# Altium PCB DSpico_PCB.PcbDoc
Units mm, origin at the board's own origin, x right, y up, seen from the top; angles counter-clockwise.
Board outline 27.22 x 32 mm, 4 copper layers (L1, L2-GND, L3-PW, L4), stack 0.77 mm thick; 44 components, 49 nets, 199 pads, 127 vias.
Unrouted connection lines stored in the file: 1.
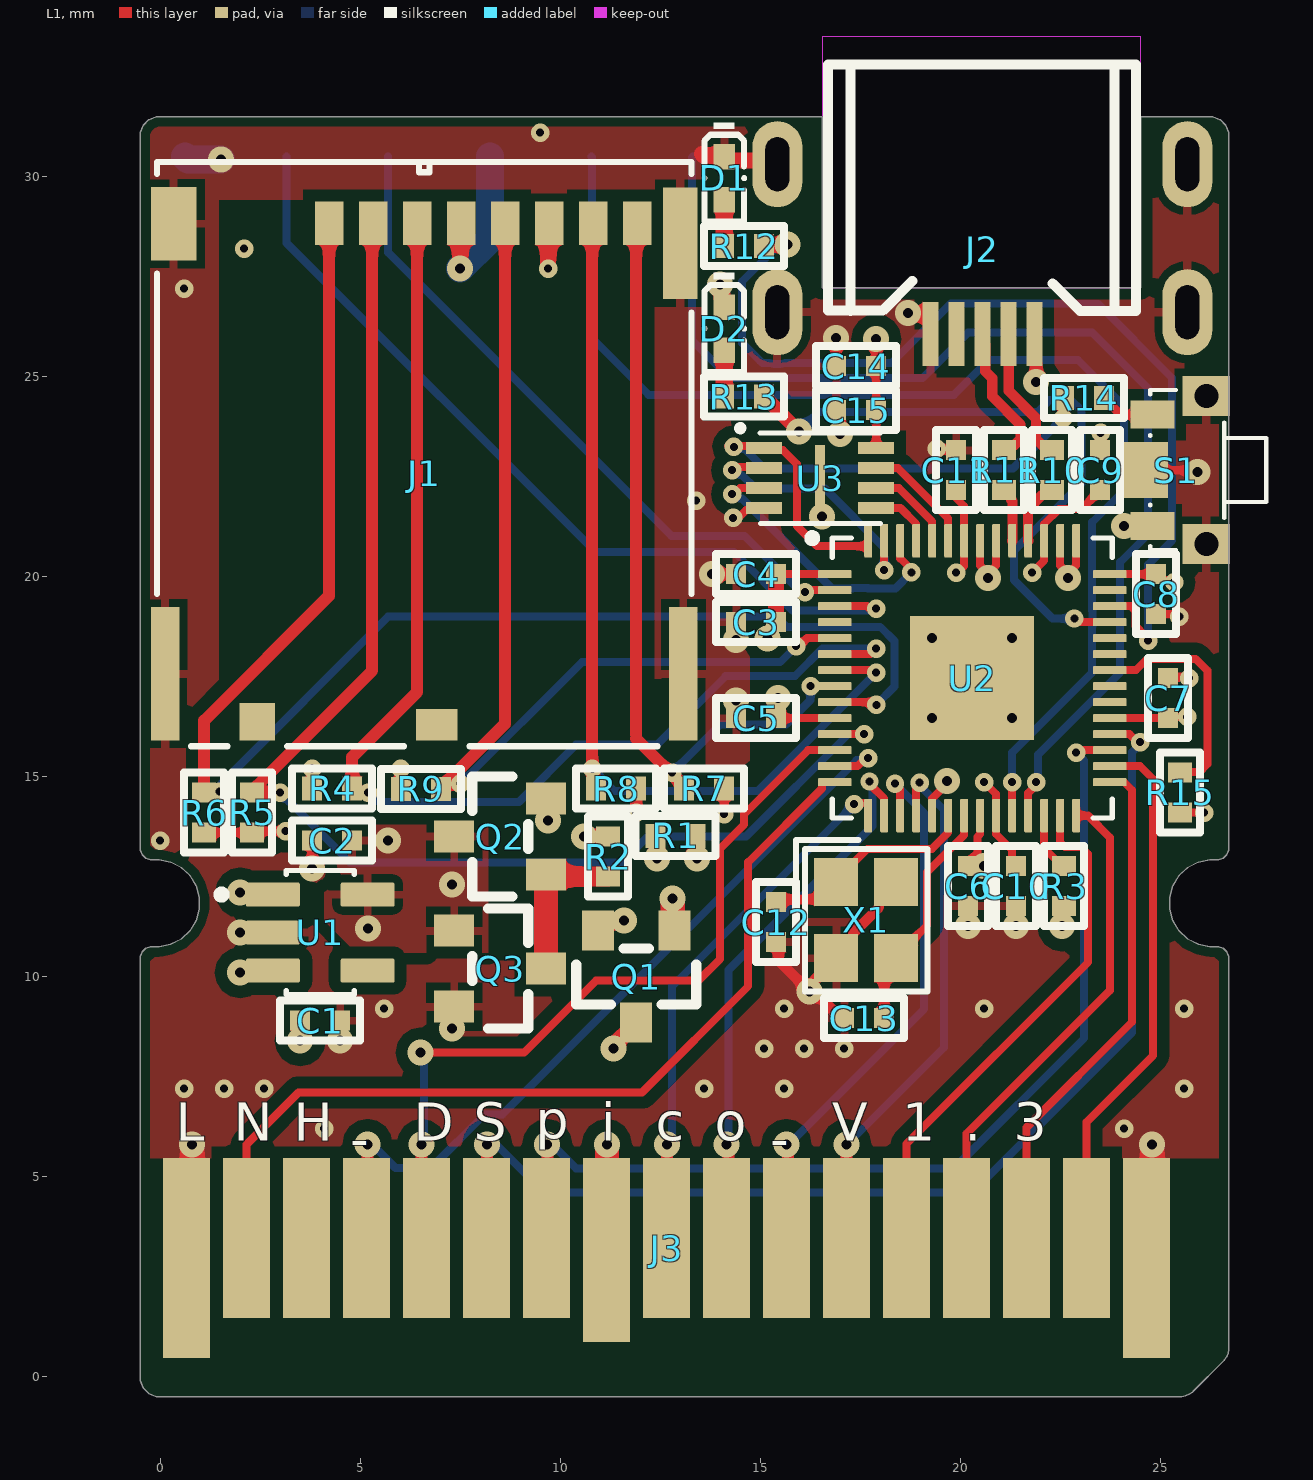
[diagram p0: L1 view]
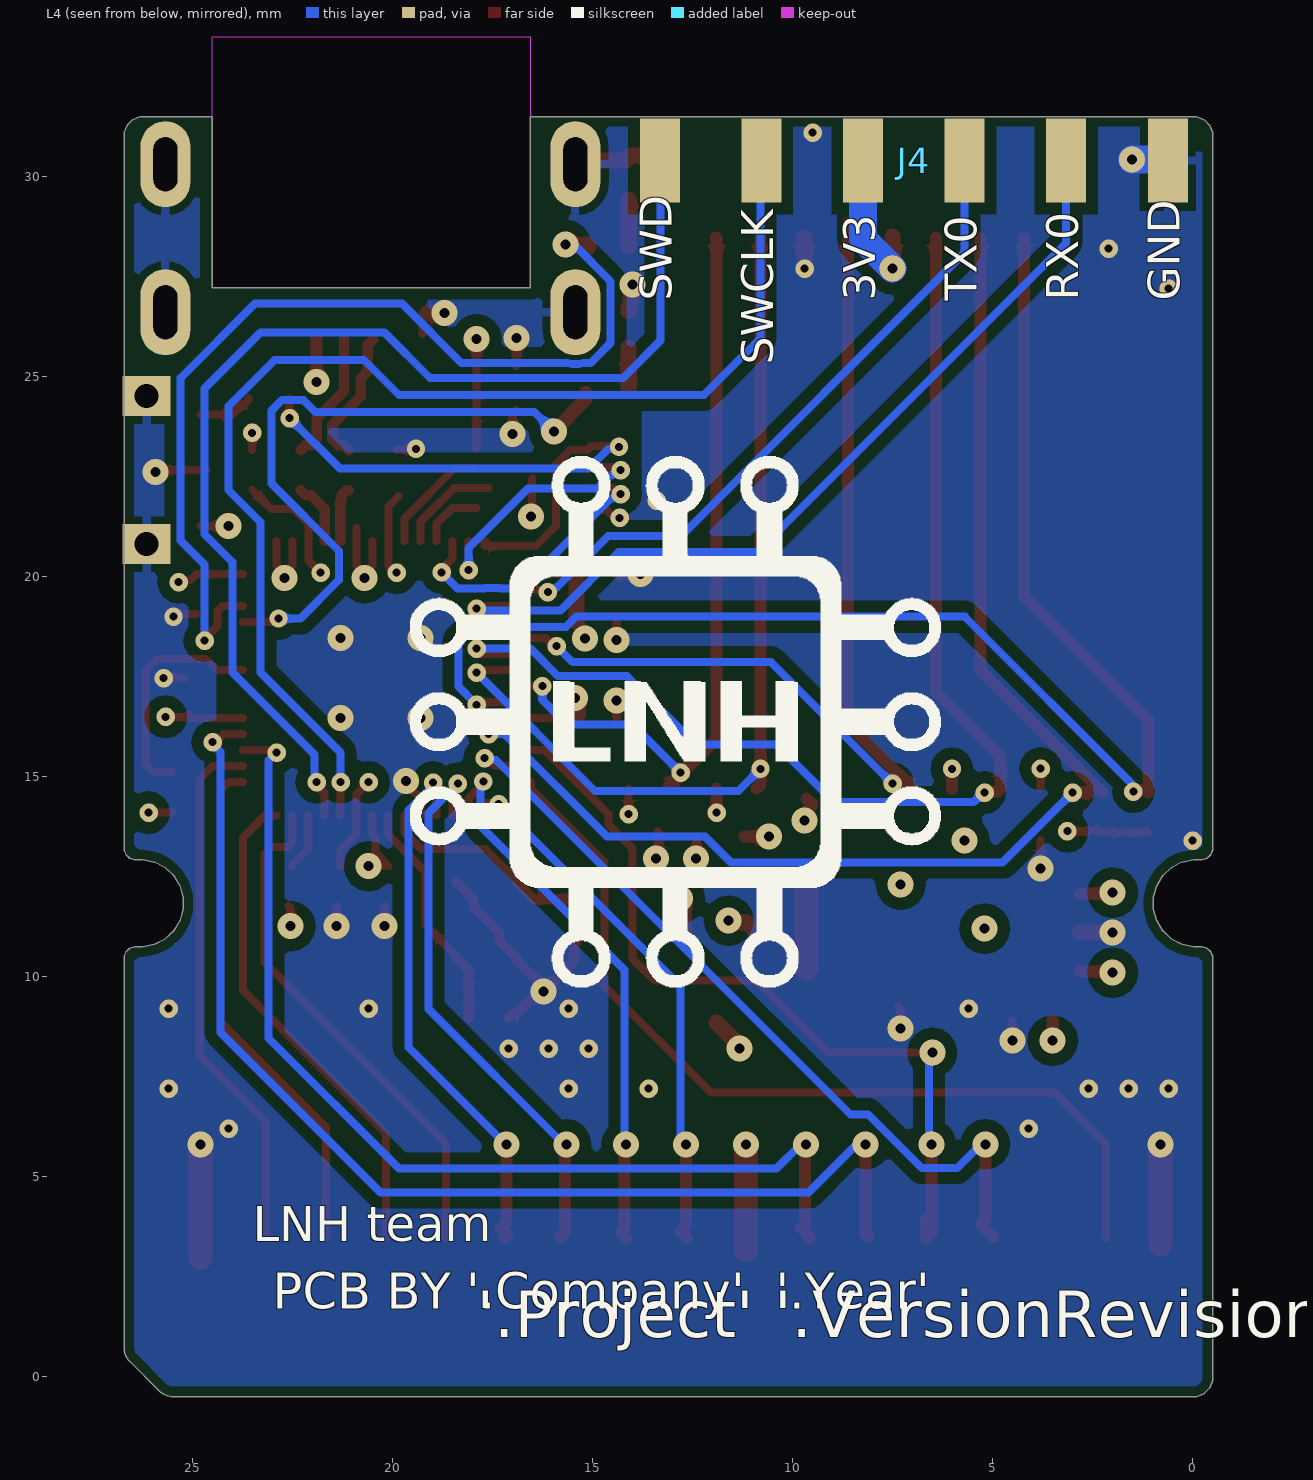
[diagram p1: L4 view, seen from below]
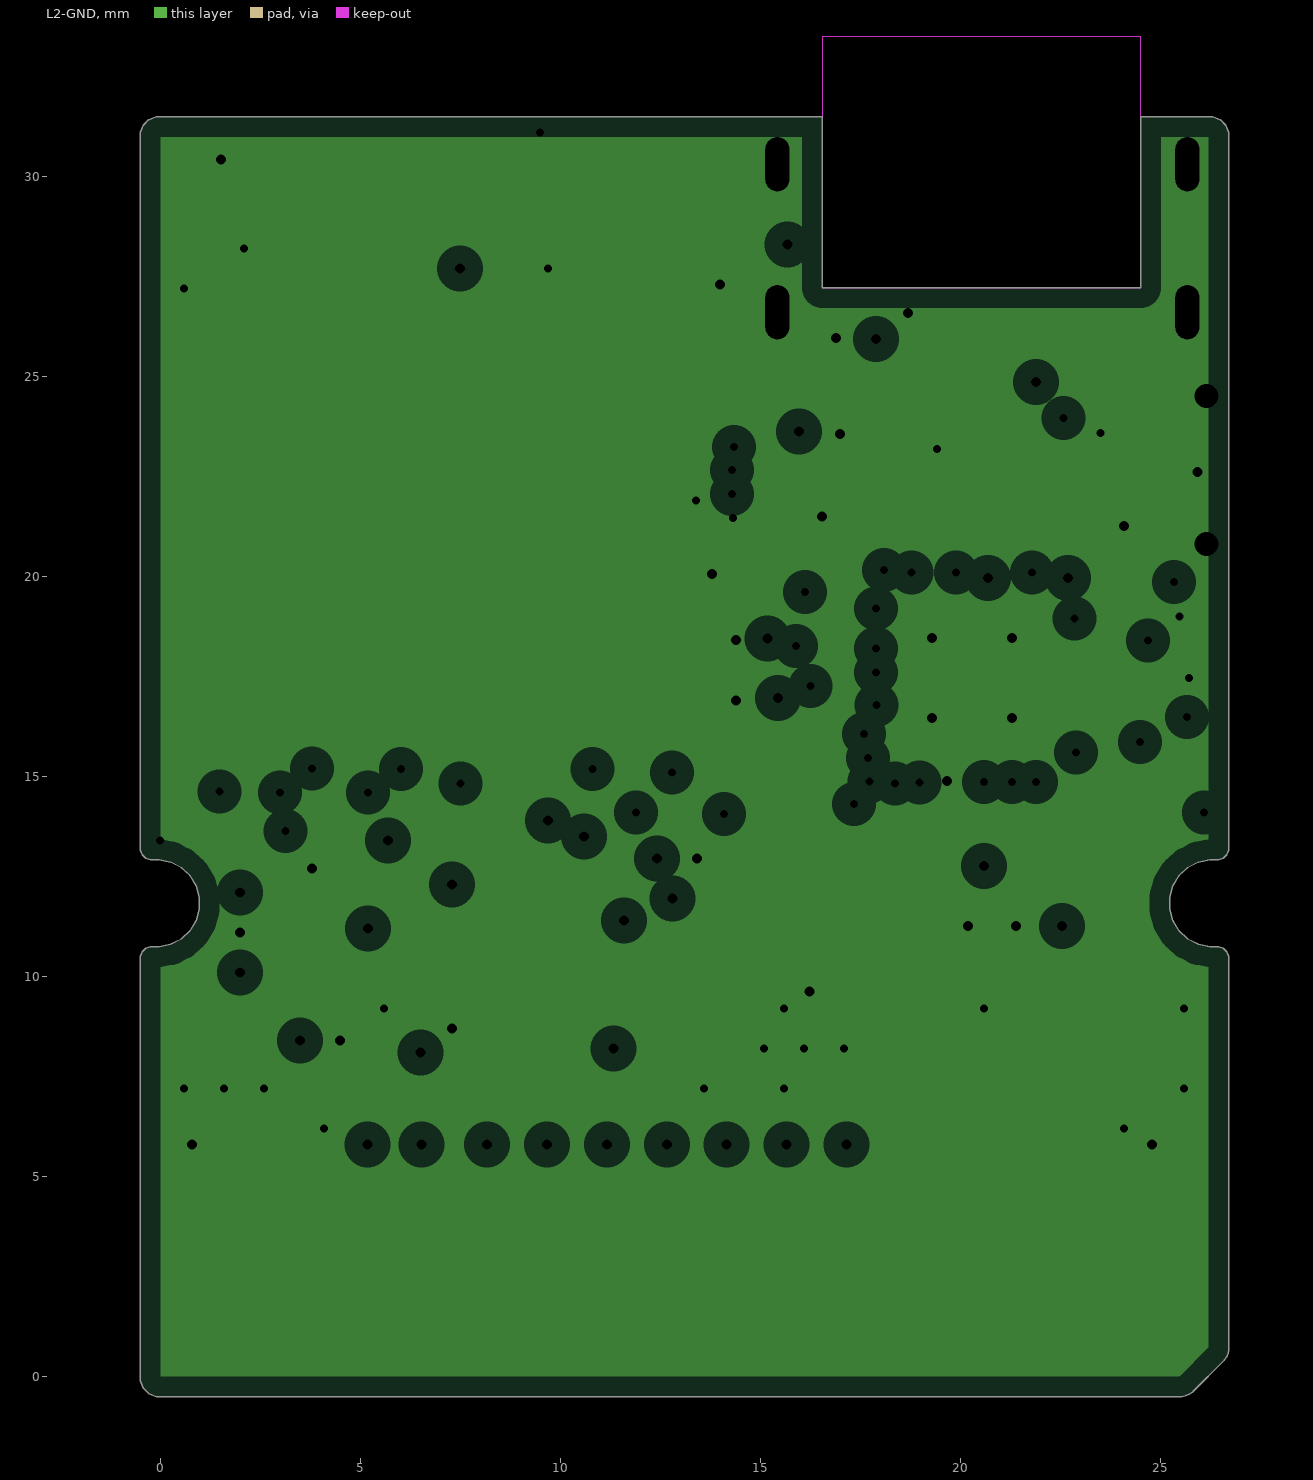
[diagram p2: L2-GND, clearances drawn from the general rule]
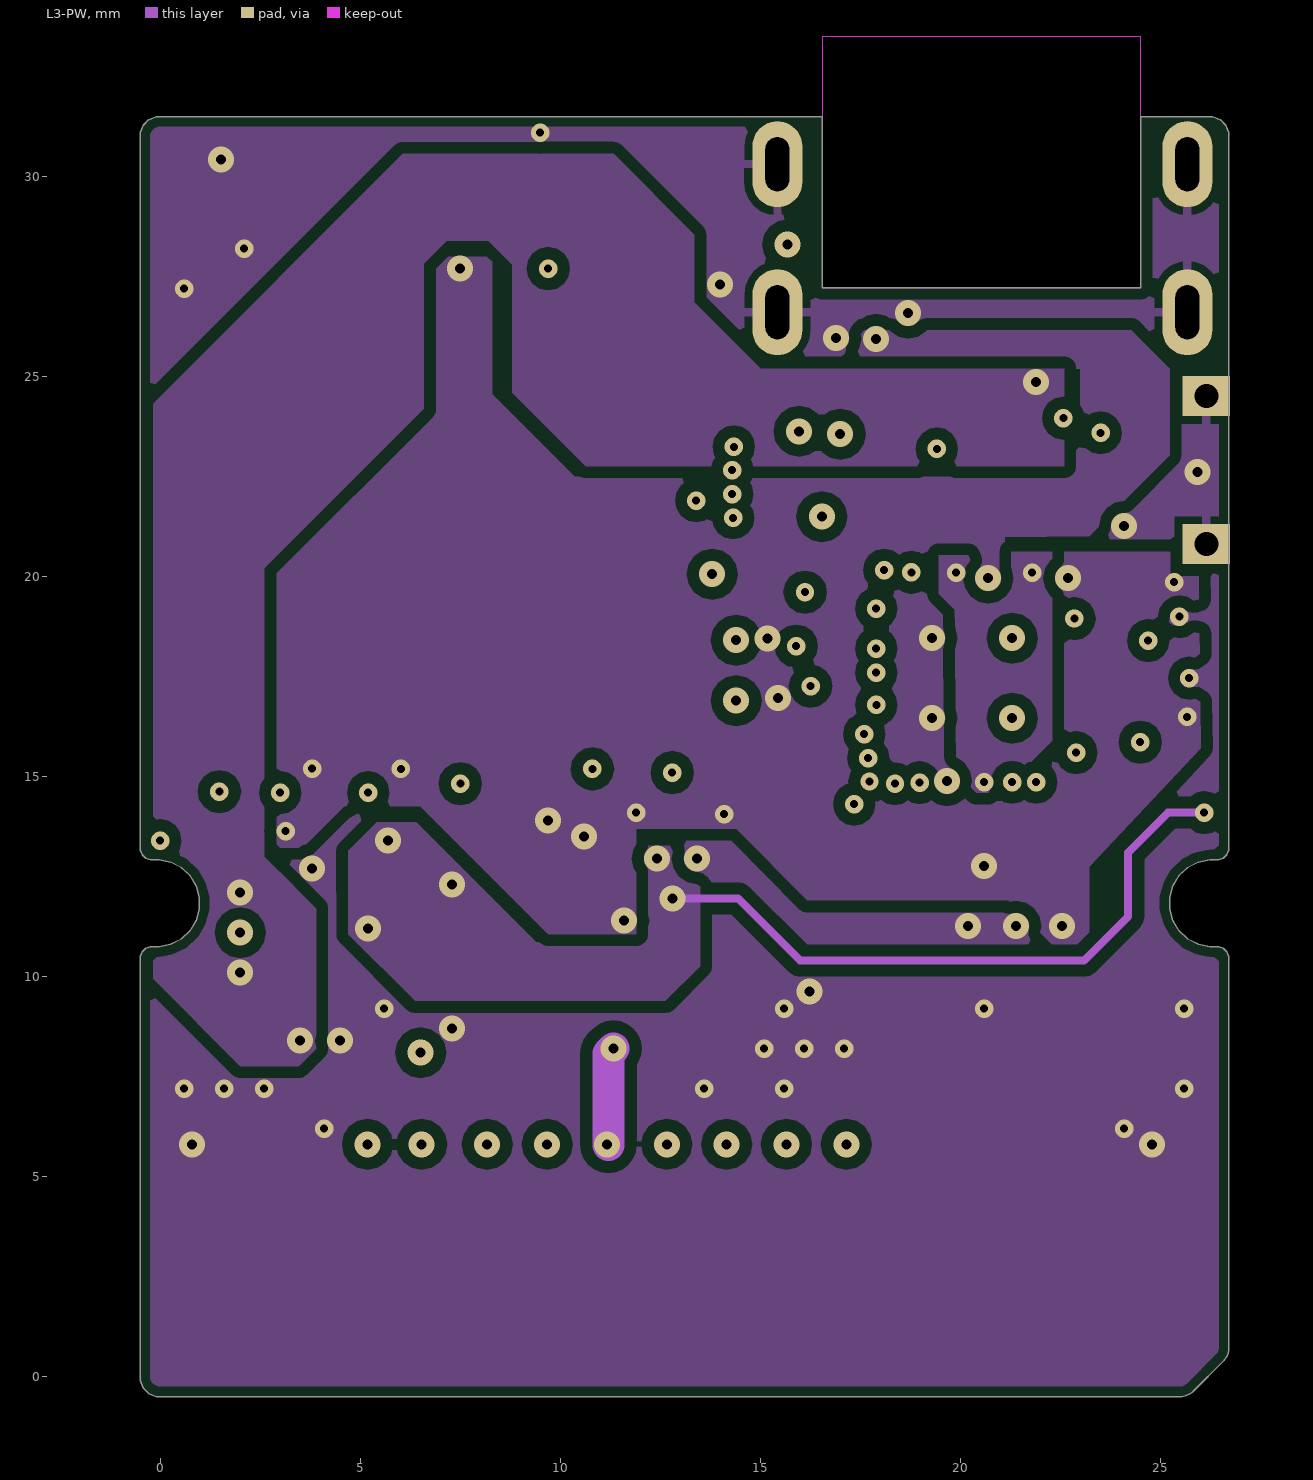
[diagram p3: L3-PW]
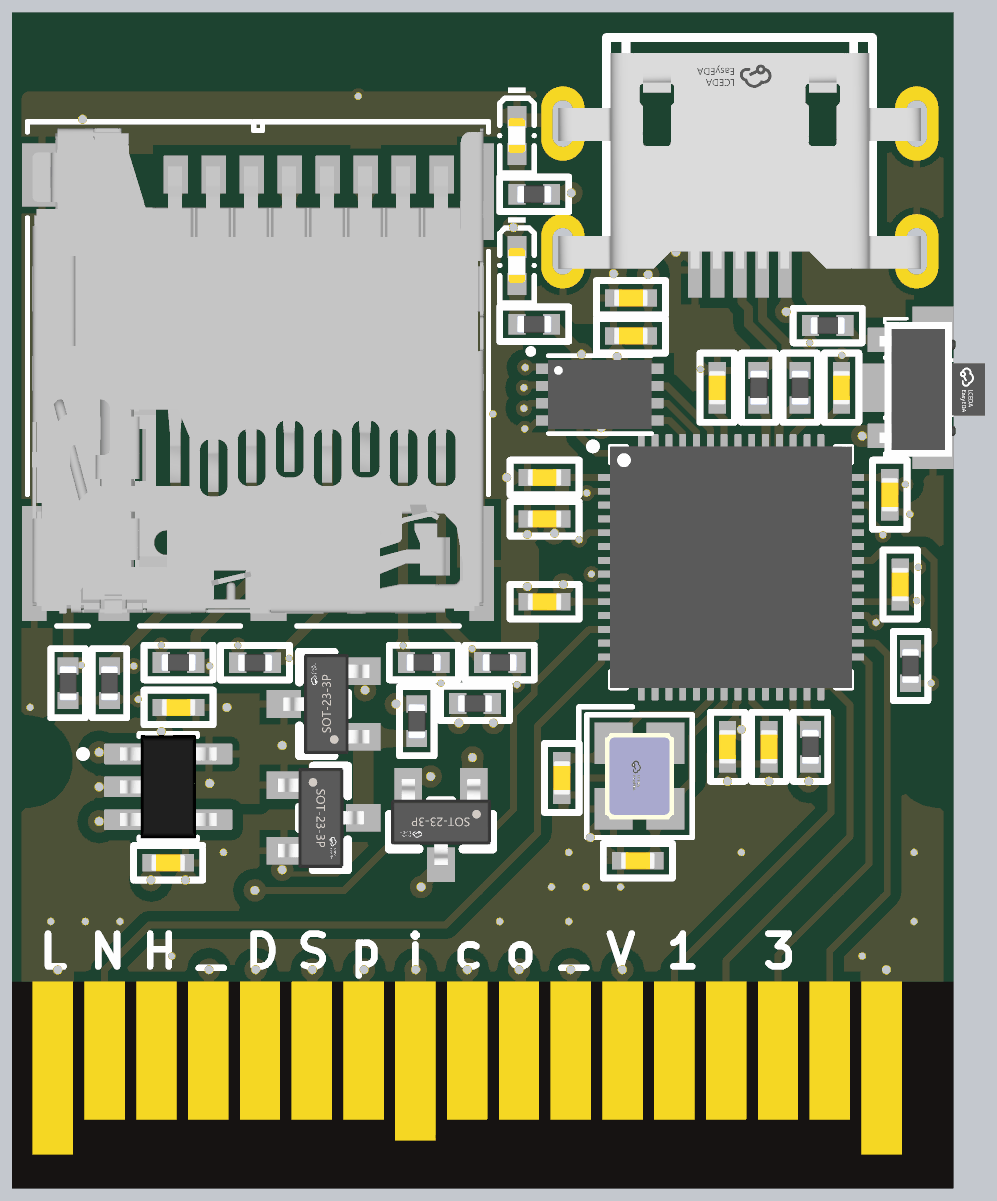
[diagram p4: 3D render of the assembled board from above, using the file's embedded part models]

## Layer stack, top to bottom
Top Solder: solder mask 0.01, Solder Resist, Dk 3.5
L1: signal copper 0.035
Dielectric 1: prepreg 0.21, PP-006, Dk 4.1
L2-GND: plane copper 0.015, net GND
Dielectric1: dielectric 0.25, FR-4, Dk 4.8
L3-PW: signal copper 0.015
Dielectric 2: prepreg 0.21, PP-006, Dk 4.1
L4: signal copper 0.035
Bottom Solder: solder mask 0.01, Solder Resist, Dk 3.5

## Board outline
-0.502,-0.101 -0.502,10.507 -0.452,10.621 -0.361,10.706 -0.243,10.748 -0.181,10.743 -0.032,10.743 0.26,10.803 0.525,10.94 0.743,11.143 0.898,11.398 0.978,11.684 0.978,11.982 0.898,12.269 0.743,12.523 0.525,12.727 0.26,12.863 -0.032,12.923 -0.181,12.923 -0.243,12.919 -0.361,12.96 -0.452,13.045 -0.502,13.16 -0.502,13.222 -0.502,31.099 -0.426,31.283 -0.285,31.424 -0.101,31.5 16.554,31.5 16.554,27.224 24.511,27.224 24.511,31.5 26.314,31.5 26.498,31.424 26.638,31.283 26.715,31.099 26.715,13.16 26.665,13.045 26.573,12.96 26.456,12.919 26.393,12.923 26.244,12.923 25.952,12.863 25.688,12.727 25.47,12.523 25.315,12.269 25.234,11.982 25.234,11.684 25.315,11.398 25.47,11.143 25.688,10.94 25.952,10.803 26.244,10.743 26.393,10.743 26.456,10.748 26.573,10.706 26.665,10.621 26.715,10.507 26.715,0.678 26.695,0.582 26.658,0.491 26.603,0.409 26.568,0.374 25.839,-0.355 25.804,-0.39 25.722,-0.445 25.631,-0.483 25.534,-0.502 25.485,-0.502 -0.002,-0.502 -0.101,-0.502 -0.285,-0.426 -0.426,-0.285

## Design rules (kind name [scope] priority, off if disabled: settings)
BoardOutlineClearance [All] p1: gap=0.25 ignorepadtopadclearanceinfootprint=FALSE except(0: Arc-SplitContinuation Track-SplitContinuation SMDPad-SplitContinuation THPad-SplitContinuation Via-SplitContinuation Fill-SplitContinuation Poly-SplitContinuation Region-SplitContinuation Text-SplitContinuation)
Clearance "Clearance poly Power Polygon" [OnLayer('L4-PWR') vs InPolygon] p1: gap=0.4 ignorepadtopadclearanceinfootprint=FALSE
Clearance Clearance-xPP-xTP-xTT [All] p2: gap=0.3 ignorepadtopadclearanceinfootprint=FALSE except(0: Arc-Hole Track-Hole SMDPad-Hole THPad-Hole Via-Hole Fill-Hole Poly-Hole Region-Hole Text-Hole; 0.125: Arc-Arc Arc-Track Arc-SMDPad Arc-THPad Arc-Via Track-Track Track-SMDPad Track-THPad Track-Via SMDPad-SMDPad SMDPad-THPad SMDPad-Via THPad-THPad THPad-Via Via-Via; 0.15: Arc-Text Track-Text SMDPad-Text THPad-Text Via-Text Fill-Text Poly-Text Region-Text Text-Text)
ComponentClearance [All] p1: gap=0 collisioncheckmode=3 verticalgap=0 showdistances=FALSE
DiffPairsRouting DiffPairsRouting_USB [All] p1: maxlimit=0.254 minlimit=0.1 mostfreqgap=0.127 toplayer_mingap=0.126 toplayer_minwidth=0.26 toplayer_maxwidth=0.861 toplayer_prefwidth=0.26 midlayer1_minwidth=0.143 midlayer1_maxwidth=0.499 midlayer1_prefwidth=0.143 bottomlayer_mingap=0.126 bottomlayer_minwidth=0.26 bottomlayer_maxwidth=0.861 bottomlayer_prefwidth=0.26 substack1={DAE5CF59-E0D9-4D6D-B9BE-EB67B8F47C43} toplayer_{dae5cf59-e0d9-4d6d-b9be-eb67b8f47c43}_mingap=0.254 toplayer_{dae5cf59-e0d9-4d6d-b9be-eb67b8f47c43}_prefgap=0.254 toplayer_{dae5cf59-e0d9-4d6d-b9be-eb67b8f47c43}_minwidth=0.26 toplayer_{dae5cf59-e0d9-4d6d-b9be-eb67b8f47c43}_maxwidth=0.861 toplayer_{dae5cf59-e0d9-4d6d-b9be-eb67b8f47c43}_prefwidth=0.26 midlayer1_{dae5cf59-e0d9-4d6d-b9be-eb67b8f47c43}_mingap=0.254 midlayer1_{dae5cf59-e0d9-4d6d-b9be-eb67b8f47c43}_prefgap=0.254 midlayer1_{dae5cf59-e0d9-4d6d-b9be-eb67b8f47c43}_minwidth=0.143 midlayer1_{dae5cf59-e0d9-4d6d-b9be-eb67b8f47c43}_maxwidth=0.499 midlayer1_{dae5cf59-e0d9-4d6d-b9be-eb67b8f47c43}_prefwidth=0.143 bottomlayer_{dae5cf59-e0d9-4d6d-b9be-eb67b8f47c43}_mingap=0.254 bottomlayer_{dae5cf59-e0d9-4d6d-b9be-eb67b8f47c43}_prefgap=0.254 bottomlayer_{dae5cf59-e0d9-4d6d-b9be-eb67b8f47c43}_minwidth=0.26 bottomlayer_{dae5cf59-e0d9-4d6d-b9be-eb67b8f47c43}_maxwidth=0.861 bottomlayer_{dae5cf59-e0d9-4d6d-b9be-eb67b8f47c43}_prefwidth=0.26 substack2={701B8A70-685D-4FFA-A794-EED23E6922A1} toplayer_{701b8a70-685d-4ffa-a794-eed23e6922a1}_mingap=0.254 toplayer_{701b8a70-685d-4ffa-a794-eed23e6922a1}_prefgap=0.254 toplayer_{701b8a70-685d-4ffa-a794-eed23e6922a1}_minwidth=0.26 toplayer_{701b8a70-685d-4ffa-a794-eed23e6922a1}_maxwidth=0.861 toplayer_{701b8a70-685d-4ffa-a794-eed23e6922a1}_prefwidth=0.26 midlayer1_{701b8a70-685d-4ffa-a794-eed23e6922a1}_mingap=0.254 midlayer1_{701b8a70-685d-4ffa-a794-eed23e6922a1}_prefgap=0.254 midlayer1_{701b8a70-685d-4ffa-a794-eed23e6922a1}_minwidth=0.143 midlayer1_{701b8a70-685d-4ffa-a794-eed23e6922a1}_maxwidth=0.499 midlayer1_{701b8a70-685d-4ffa-a794-eed23e6922a1}_prefwidth=0.143 bottomlayer_{701b8a70-685d-4ffa-a794-eed23e6922a1}_mingap=0.254 bottomlayer_{701b8a70-685d-4ffa-a794-eed23e6922a1}_prefgap=0.254 bottomlayer_{701b8a70-685d-4ffa-a794-eed23e6922a1}_minwidth=0.26 bottomlayer_{701b8a70-685d-4ffa-a794-eed23e6922a1}_maxwidth=0.861 bottomlayer_{701b8a70-685d-4ffa-a794-eed23e6922a1}_prefwidth=0.26 substack3={F6D6EC32-38D3-4AFD-B5CD-3CE99868ACF7} toplayer_{f6d6ec32-38d3-4afd-b5cd-3ce99868acf7}_mingap=0.254 toplayer_{f6d6ec32-38d3-4afd-b5cd-3ce99868acf7}_prefgap=0.254 toplayer_{f6d6ec32-38d3-4afd-b5cd-3ce99868acf7}_minwidth=0.26 toplayer_{f6d6ec32-38d3-4afd-b5cd-3ce99868acf7}_maxwidth=0.861 toplayer_{f6d6ec32-38d3-4afd-b5cd-3ce99868acf7}_prefwidth=0.26 midlayer1_{f6d6ec32-38d3-4afd-b5cd-3ce99868acf7}_mingap=0.254 midlayer1_{f6d6ec32-38d3-4afd-b5cd-3ce99868acf7}_prefgap=0.254 midlayer1_{f6d6ec32-38d3-4afd-b5cd-3ce99868acf7}_minwidth=0.143 midlayer1_{f6d6ec32-38d3-4afd-b5cd-3ce99868acf7}_maxwidth=0.499 midlayer1_{f6d6ec32-38d3-4afd-b5cd-3ce99868acf7}_prefwidth=0.143 bottomlayer_{f6d6ec32-38d3-4afd-b5cd-3ce99868acf7}_mingap=0.254 bottomlayer_{f6d6ec32-38d3-4afd-b5cd-3ce99868acf7}_prefgap=0.254 bottomlayer_{f6d6ec32-38d3-4afd-b5cd-3ce99868acf7}_minwidth=0.26 bottomlayer_{f6d6ec32-38d3-4afd-b5cd-3ce99868acf7}_maxwidth=0.861 bottomlayer_{f6d6ec32-38d3-4afd-b5cd-3ce99868acf7}_prefwidth=0.26 substack4={6221F06C-9483-4E26-967B-27528F2B8686} toplayer_{6221f06c-9483-4e26-967b-27528f2b8686}_mingap=0.254 toplayer_{6221f06c-9483-4e26-967b-27528f2b8686}_prefgap=0.254 toplayer_{6221f06c-9483-4e26-967b-27528f2b8686}_minwidth=0.26 toplayer_{6221f06c-9483-4e26-967b-27528f2b8686}_maxwidth=0.861 toplayer_{6221f06c-9483-4e26-967b-27528f2b8686}_prefwidth=0.26 midlayer1_{6221f06c-9483-4e26-967b-27528f2b8686}_mingap=0.254 midlayer1_{6221f06c-9483-4e26-967b-27528f2b8686}_prefgap=0.254 midlayer1_{6221f06c-9483-4e26-967b-27528f2b8686}_minwidth=0.143 midlayer1_{6221f06c-9483-4e26-967b-27528f2b8686}_maxwidth=0.499 midlayer1_{6221f06c-9483-4e26-967b-27528f2b8686}_prefwidth=0.143 bottomlayer_{6221f06c-9483-4e26-967b-27528f2b8686}_mingap=0.254 bottomlayer_{6221f06c-9483-4e26-967b-27528f2b8686}_prefgap=0.254 bottomlayer_{6221f06c-9483-4e26-967b-27528f2b8686}_minwidth=0.26 bottomlayer_{6221f06c-9483-4e26-967b-27528f2b8686}_maxwidth=0.861 bottomlayer_{6221f06c-9483-4e26-967b-27528f2b8686}_prefwidth=0.26 impedanceprofiledriven=TRUE impedanceprofileid={773E90AA-7B5E-4F0F-963B-D0F3BC933954} impedanceprofilevalue=90.000000 maxuncoupledlength=12.7
Height [All] p1: minheight=0 maxheight=25 prefheight=12.5
HoleSize HoleSize-PTH [All] p1: absolutevalues=TRUE maxlimit=4 minlimit=0.15 maxpercent=80.000 minpercent=20.000
HoleToHoleClearance [All] p1: gap=0.35 allowstackedmicrovias=TRUE
MatchedLengths MatchedLengths_USB_DiffPairs_1 [InxSignalClass('USB_CHJ1_1_DL') OR InxSignalClass('USB_CHJ1_1_RX') OR InxSignalClass('USB_CHJ1_1_TX')] p1: tolerance=0.127 checknetsindiffpair=TRUE checkdiffpairvsdiffpair=FALSE checkxsignals=FALSE checkothers=FALSE
MatchedLengths MatchedLengths_USB_DiffPairs [InxSignalClass('USB_CHJ1_1_DL') OR InxSignalClass('USB_CHJ1_1_RX') OR InxSignalClass('USB_CHJ1_1_TX')] p2: tolerance=0.127 checknetsindiffpair=TRUE checkdiffpairvsdiffpair=FALSE checkxsignals=FALSE checkothers=FALSE
MatchedLengths DiffPairClass [InDifferentialPairClass('All Differential Pairs')] p3: tolerance=0.127 checknetsindiffpair=TRUE checkdiffpairvsdiffpair=FALSE checkxsignals=FALSE checkothers=FALSE
MatchedLengths MatchedLengths_GBE0 [InNetClass('GBE0')] p4: tolerance=0.127 checknetsindiffpair=FALSE checkdiffpairvsdiffpair=TRUE checkxsignals=TRUE checkothers=TRUE
MatchedLengths MatchedLengths_GBE1 [InNetClass('GBE1')] p5: tolerance=0.127 checknetsindiffpair=FALSE checkdiffpairvsdiffpair=TRUE checkxsignals=TRUE checkothers=TRUE
MatchedLengths MatchedLengths_GBE2 [InNetClass('GBE2')] p6: tolerance=0.127 checknetsindiffpair=FALSE checkdiffpairvsdiffpair=TRUE checkxsignals=TRUE checkothers=TRUE
MatchedLengths MatchedLengths_HDMI [InNetClass('HDMI')] p7: tolerance=0.127 checknetsindiffpair=FALSE checkdiffpairvsdiffpair=TRUE checkxsignals=TRUE checkothers=TRUE
MatchedLengths MatchedLengths_USB-GBE [InNetClass('USB-GBE')] p8: tolerance=0.127 checknetsindiffpair=FALSE checkdiffpairvsdiffpair=TRUE checkxsignals=TRUE checkothers=TRUE
MatchedLengths MatchedLengths_USB3 [InNetClass('USB3')] p9: tolerance=0.127 checknetsindiffpair=FALSE checkdiffpairvsdiffpair=TRUE checkxsignals=TRUE checkothers=TRUE
MatchedLengths MatchedLengths_USB2 [InNetClass('USB2')] p10: tolerance=0.127 checknetsindiffpair=FALSE checkdiffpairvsdiffpair=TRUE checkxsignals=TRUE checkothers=TRUE
MatchedLengths MatchedLengths_DS [InNetClass('D[7..0]')] p11: tolerance=0.127 checknetsindiffpair=FALSE checkdiffpairvsdiffpair=TRUE checkxsignals=TRUE checkothers=TRUE
MinimumAnnularRing "Minimum IAR  >0.45mm" [((ObjectKind = 'Pad') OR (ObjectKind = 'Via')) And (Layer = 'MultiLayer') And (HoleDiameter > AsMM(0.45))] p1: minimumring=0.13 // minimum inner annular ring for pads > 0.45mm finished hole size
MinimumAnnularRing "Minimum IAR <=0.45mm" [((ObjectKind = 'Pad') OR (ObjectKind = 'Via')) And (Layer = 'MultiLayer') And (HoleDiameter <= AsMM(0.45))] p2: minimumring=0.13 // minimum inner annular ring for pads <= 0.45mm finished hole size
MinimumSolderMaskSliver [All] p1: minsoldermaskwidth=0.08
PlaneClearance PlaneClearance-IPI [All] p1: clearance=0.45
PlaneConnect PlaneConnect_PWR [HasFootprint('NDS_CARD')] p1: planeconnectstyle=Direct reliefexpansion=0.175 reliefentries=2 reliefconductorwidth=0.2 reliefairgap=0.2
PlaneConnect PlaneConnect_NDS [HasFootprint('NDS_CARD')] p2: planeconnectstyle=Direct reliefexpansion=0.175 reliefentries=2 reliefconductorwidth=0.2 reliefairgap=0.2
PlaneConnect PlaneConnect_VIA [IsVia] p3: planeconnectstyle=Direct reliefexpansion=0.175 reliefentries=4 reliefconductorwidth=0.2 reliefairgap=0.2
PlaneConnect [All] p4: planeconnectstyle=Relief reliefexpansion=0.2 reliefentries=4 reliefconductorwidth=0.25 reliefairgap=0.2
PolygonConnect PolygonConnect_VIA [HasFootprint('NET_TIE')] p1: connectstyle=Direct reliefconductorwidth=0.2 reliefentries=4 polygonreliefangle="90 Angle" airgapwidth=0.2
PolygonConnect PolygonConnect_NDS [HasFootprint('NDS_CARD')] p2: connectstyle=Direct reliefconductorwidth=0.2 reliefentries=4 polygonreliefangle="90 Angle" airgapwidth=0.2
PolygonConnect PolygonConnect_VIA_1 [All] p3: thpad.connectstyle=Relief thpad.reliefconductorwidth=0.2 thpad.reliefentries=4 thpad.polygonreliefangle="90 Angle" thpad.airgapwidth=0.2 smdpad.connectstyle=Relief smdpad.reliefconductorwidth=0.2 smdpad.reliefentries=4 smdpad.polygonreliefangle="90 Angle" smdpad.airgapwidth=0.2 via.connectstyle=Direct via.reliefconductorwidth=0.2 via.reliefentries=4 via.polygonreliefangle="90 Angle" via.airgapwidth=0.2
PolygonConnect PolygonConnect_SMD [Not HasFootprint('NET_TIE') and InNet('AGND')] p4: thpad.connectstyle=Direct thpad.reliefconductorwidth=0.2 thpad.reliefentries=4 thpad.polygonreliefangle="90 Angle" thpad.airgapwidth=0.2 smdpad.connectstyle=Relief smdpad.reliefconductorwidth=0.2 smdpad.reliefentries=4 smdpad.polygonreliefangle="90 Angle" smdpad.airgapwidth=0.2 via.connectstyle=Direct via.reliefconductorwidth=0.2 via.reliefentries=4 via.polygonreliefangle="90 Angle" via.airgapwidth=0.2
PolygonConnect [All] p5: connectstyle=Relief reliefconductorwidth=0.25 reliefentries=4 polygonreliefangle="90 Angle" airgapwidth=0.2
RoutingCorners [All] p1: cornerstyle=45-Degree minsetback=2.5 maxsetback=2.5
RoutingVias "RoutingVias > 0.45mm" [(ObjectKind = 'Via') And (HoleDiameter > AsMM(0.45))] p1: holewidth=0.5 width=0.85 viastyle="Through Hole" minholewidth=0.5 minwidth=0.85 maxholewidth=0.9 maxwidth=1.25 // finishet hole size > 0.45mm
RoutingVias "RoutingVias <= 0.45mm" [(ObjectKind = 'Via') And (HoleDiameter <= AsMM(0.45))] p2: holewidth=0.2 width=0.55 viastyle="Through Hole" minholewidth=0.15 minwidth=0.5 maxholewidth=0.45 maxwidth=0.8 // finishet hole size <= 0.45mm
SilkToSilkClearance [All] p1: silktosilkclearance=0.1
SilkToSolderMaskClearance SilkscreenOverComponentPads [IsPad] p1: minsilkscreentomaskgap=0.1 clearancetoexposedcopper=TRUE
SolderMaskExpansion [All] p1: expansion=0 istentingtop=FALSE
UnRoutedNet [All] p1: checkbadconnections=TRUE
Width Width-xTW [All] p1: maxlimit=5 minlimit=0.125 preferedwidth=0.15
Width Width-GigaE [All] p2: maxlimit=0.15 minlimit=0.15 preferedwidth=0.15
Width Width-Power [InNetClass('PWR')] p3: maxlimit=5 minlimit=0.2 preferedwidth=0.25
18 further rules are at their usual default settings.

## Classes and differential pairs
net class D[7..0]: D0 D1 D2 D3 D4 D5 D6 D7
differential pair D: +D_P -D_N
differential pair USB_D: +USB_D_P -USB_D_N

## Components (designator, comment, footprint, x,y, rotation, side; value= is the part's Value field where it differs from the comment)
C1 "1uF" C0402 4,8.9 r180 top
C2 "1uF" C0402 4.3,13.4 r0 top
C3 "1uF" C0402 14.9,18.86 r0 top
C4 "100NF" C0402 14.9,20.06 r0 top
C5 "100NF" C0402 14.9,16.46 r0 top
C6 "100NF" C0402 20.2,12.26 r90 top
C7 "100NF" C0402 25.2,16.96 r270 top
C8 "100NF" C0402 24.9,19.56 r90 top
C9 "1uF" C0402 23.5,22.66 r270 top
C10 "100NF" C0402 21.4,12.26 r90 top
C11 "100NF" C0402 19.9,22.66 r270 top
C12 "12PF" C0402 15.4,11.36 r90 top
C13 "12PF" C0402 17.6,8.96 r0 top
C14 "2.2uF" C0402 17.4,25.26 r0 top
C15 "100NF" C0402 17.4,24.16 r0 top
D1 "BL-HB337A-AV-TRB" LED0402-RD 14.1,29.96 r270 top
D2 "BL-HUB37A-AV-TRB" LED0402-RD 14.1,26.2 r270 top
J1 "5033981892" 503398-1892_MOL 6.6,23.06 r0 top
J2 "920-F62A2021S10101" MICRO-USB_MICRO-USB-31 20.2,29.86 r90 top locked
J3 "NDS_CARDA" NDS_CARD 0.659,2.959 r0 top
J4 "DSPICO-DEV-PORT" EP_DEV_PORT 13.32,30.4 r180 bottom
Q1 "SI2307CDS-T1-E3" SOT-23_L2.9-W1.3-P1.90-LS2.4-BR 11.9,10 r90 top
Q2 "SI2307CDS-T1-E3" SOT-23_L2.9-W1.3-P1.90-LS2.4-BR 8.5,13.5 r0 top locked
Q3 "2N7002KQ-7" SOT-23_L2.9-W1.3-P1.90-LS2.4-BR 8.5,10.2 r180 top
R1 "100K" R0402 12.883,13.517 r0 top
R2 "100K" R0402 11.2,13 r90 top
R3 "10K" R0402 22.6,12.26 r270 top
R4 "10K" R0402 4.3,14.7 r180 top
R5 "10K" R0402 2.3,14.1 r270 top
R6 "10K" R0402 1.1,14.1 r270 top
R7 "10K" R0402 13.6,14.7 r0 top
R8 "10K" R0402 11.4,14.7 r0 top
R9 "10K" R0402 6.516,14.695 r180 top
R10 "RC0402FR-0727RL" R0402 22.3,22.66 r270 top value=27
R11 "RC0402FR-0727RL" R0402 21.1,22.66 r270 top value=27
R12 "120R" R0402 14.6,28.26 r0 top
R13 "220R" R0402 14.6,24.5 r0 top
R14 "1K" R0402 23.1,24.46 r180 top
R15 "1K" R0402 25.5,14.6 r90 top
S1 "SKTDLDE010" KEY-SMD_SKTDLDE010 25.4,22.66 r270 top
U1 "AP2112K-3.3TRG1" SOT95P285X140-5N 4,11.1 r0 top
U2 "RP2040" QFN40P700X700X90-57N 20.3,17.46 r0 top locked
U3 "W25Q16JVUXIQ" SON50P300X200X60-9N 16.5,22.46 r0 top
X1 "XYDBPCNANF-12MHZ" OSC-SMD_4P-L2.5-W2.0-BL 17.65,11.41 r270 top

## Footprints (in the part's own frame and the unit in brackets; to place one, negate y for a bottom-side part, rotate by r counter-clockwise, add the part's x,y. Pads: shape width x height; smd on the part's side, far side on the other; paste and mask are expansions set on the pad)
503398-1892_MOL [mil]
  rect 28x43 smd: 1(-93.7,227.38) 2(-50.39,227.38) 3(-7.09,227.38) 4(36.22,227.38) 5(79.53,227.38) 6(122.83,227.38) 7(166.14,227.38) 8(209.45,227.38)
  rect 35x37 smd: 9(-164.17,-263.37)
  rect 41x31 smd: 10(12.2,-266.32)
  rect 45x72 smd: 11(-246.46,226.79)
  rect 34x110 smd: 12(251.97,207.7)
  rect 28x131 smd: 13(-255.12,-216.12) 14(255.12,-216.12)
  silkscreen extent -263,-288 263,288, body extent -258,-273 258,280, height 50
C0402 [mm]
  rect 0.5x0.5 smd: 1(-0.5,0) 2(0.5,0)
  silkscreen extent -1,-0.5 1,0.5, body extent -0.5,-0.25 0.5,0.25, height 0.56
EP_DEV_PORT [mm] "Exposed DSpico Development port"
  rect 1x2.1 smd paste-1: 1(0,0) 2(2.54,0) 3(5.08,0) 4(7.62,0) 5(10.16,0) 6(12.7,0)
KEY-SMD_SKTDLDE010 [mm]
  rect 0.7x1.1 smd: 1(1.39,-0.596) 2(-1.388,-0.597)
  rect 1.4x1.1 smd: 3(0,-0.75)
  rect 1x1.2 hole 0.6: 4(-1.85,0.75) 4(1.85,0.75)
  silkscreen extent -2,-0.65 2,2.25, body extent -1.9,-0.8 2,2.25, height 1.54
LED0402-RD [mm]
  rect 0.636x0.54 smd: 1(-0.538,0) 2(0.538,0)
  silkscreen extent -1.39,-0.54 1.09,0.54, body extent -0.51,-0.26 0.51,0.25, height 0.19
MICRO-USB_MICRO-USB-31 [mm]
  rect 1.6x0.4 smd: 1(-3.791,-1.655) 2(-3.791,-1.005) 3(-3.791,-0.354) 4(-3.791,0.296) 5(-3.791,0.946)
  oval 2.15x1.25 hole 0.6 slot 1.35 at 0 deg: 6(-3.251,-5.479) 7(0.449,-5.479) 8(-3.251,4.771) 9(0.449,4.771)
  Keep-Out Layer board cut-out: -2.637,3.646 -2.637,-4.311 3.638,-4.311 3.638,3.646
  silkscreen extent -3.22,-4.19 2.94,3.51, body extent -3.75,-5.6 2.5,4.9, height 1.78
NDS_CARD [mm] "NDS_CARD"
  rect 1.17x5 smd paste-1: 1(0,0) 17(24,0)
  rect 1.17x4 smd paste-1: 2(1.5,0.5) 3(3,0.5) 4(4.5,0.5) 5(6,0.5) 6(7.5,0.5) 7(9,0.5) 9(12,0.5) 10(13.5,0.5) 11(15,0.5) 12(16.5,0.5) 13(18,0.5) 14(19.5,0.5) 15(21,0.5) 16(22.5,0.5)
  rect 1.17x4.6 smd paste-1: 8(10.5,0.2)
  L1 pour cut-out: -1.575,2.5 26.65,2.5 26.65,-3.975 -1.575,-3.975
OSC-SMD_4P-L2.5-W2.0-BL [mm]
  rect 1.2x1.1 smd: 1(-0.95,-0.75) 2(0.95,-0.75) 3(0.95,0.75) 4(-0.95,0.75)
  silkscreen extent -2.01,-1.76 1.78,1.53, body extent -1.25,-1 1.25,1, height 0.55
QFN40P700X700X90-57N [mm]
  rrect25% 0.84x0.2 smd: 1(-3.435,2.6) 2(-3.435,2.2) 3(-3.435,1.8) 4(-3.435,1.4) 5(-3.435,1) 6(-3.435,0.6) 7(-3.435,0.2) 8(-3.435,-0.2) 9(-3.435,-0.6) 10(-3.435,-1) 11(-3.435,-1.4) 12(-3.435,-1.8) 13(-3.435,-2.2) 14(-3.435,-2.6) 29(3.435,-2.6) 30(3.435,-2.2) 31(3.435,-1.8) 32(3.435,-1.4) 33(3.435,-1) 34(3.435,-0.6) 35(3.435,-0.2) 36(3.435,0.2) 37(3.435,0.6) 38(3.435,1) 39(3.435,1.4) 40(3.435,1.8) 41(3.435,2.2) 42(3.435,2.6)
  rrect25% 0.2x0.84 smd: 15(-2.6,-3.435) 16(-2.2,-3.435) 17(-1.8,-3.435) 18(-1.4,-3.435) 19(-1,-3.435) 20(-0.6,-3.435) 21(-0.2,-3.435) 22(0.2,-3.435) 23(0.6,-3.435) 24(1,-3.435) 25(1.4,-3.435) 26(1.8,-3.435) 27(2.2,-3.435) 28(2.6,-3.435) 43(2.6,3.435) 44(2.2,3.435) 45(1.8,3.435) 46(1.4,3.435) 47(1,3.435) 48(0.6,3.435) 49(0.2,3.435) 50(-0.2,3.435) 51(-0.6,3.435) 52(-1,3.435) 53(-1.4,3.435) 54(-1.8,3.435) 55(-2.2,3.435) 56(-2.6,3.435)
  rect 3.1x3.1 smd paste-0.57: 57(0,0)
  silkscreen extent -4.1,-3.5 3.5,3.6, body extent -3.5,-3.5 3.5,3.5, height 0.9
R0402 [mm]
  rect 0.5x0.6 smd: 1(-0.5,0) 2(0.5,0)
  silkscreen extent -1,-0.5 1,0.5, body extent -0.5,-0.25 0.5,0.25, height 0.4
SON50P300X200X60-9N [mm]
  rect 0.9x0.3 smd: 1(-1.4,0.75) 2(-1.4,0.25) 3(-1.4,-0.25) 4(-1.4,-0.75) 5(1.4,-0.75) 6(1.4,-0.25) 7(1.4,0.25) 8(1.4,0.75)
  rect 0.25x1.65 smd: 9(0,0)
  silkscreen extent -2.08,-1.13 1.51,1.33, body extent -1.5,-1 1.5,1, height 0.6
SOT95P285X140-5N [mm]
  rrect15% 1.35x0.6 smd: 1(-1.185,0.95) 2(-1.185,0) 3(-1.185,-0.95) 4(1.185,-0.95) 5(1.185,0.95)
  silkscreen extent -2.57,-1.55 0.85,1.55, body extent -1.4,-1.5 1.4,1.5, height 1.15
SOT-23_L2.9-W1.3-P1.90-LS2.4-BR [mm]
  rect 1x0.8 smd: 1(1.15,-0.95) 2(1.15,0.95) 3(-1.15,0)
  silkscreen extent -0.7,-1.5 0.7,1.5, body extent -1.17,-1.45 1.33,1.44, height 1.03

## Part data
C1 C2 C3 C9: library part C1005X5R1E105K050BC, "TDK - C1005X5R1E105K050BC - COND, CERÁ MULT, X5R, 1UF, 25V, 0402", Case Code (Imperial)=0402, Case Code (Metric)=1005, Dielectric=X5R, Dielectric Material=Ceramic, Manufacturer=TDK, Max Operating Temperature=85°C, Min Operating Temperature=-55°C, Package Quantity=1, Supplier Part Number 1=2346884, Tolerance=10%, Voltage Rating=25V
C4 C5 C6 C7 C8 C10 C11 C15: library part GRM155R71C104KA88D, "0402 0.1 uF 16V ±10 % Tolerance X7R SMT Multilayer Ceramic Capacitor", Capacitance=100nF, Case Code (Imperial)=0402, Case Code (Metric)=1005, Dielectric=X7R, Dielectric Material=Ceramic, Insulation Resistance=10GR, Manufacturer=Murata, Max Operating Temperature=125°C, Min Operating Temperature=-55°C, Package Quantity=1, Supplier Part Number 1=490-3261-1-ND, Tolerance=10%, Voltage=16V
C12 C13: library part 04025A120JAT2A, "CAP CER 12PF 50V C0G/NP0 0402", Capacitance=12pF, Case Code (Imperial)=0402, Case Code (Metric)=1005, Dielectric=C0G, Insulation Resistance=100GR, Manufacturer="Kyocera AVX", Max Operating Temperature=125°C, Min Operating Temperature=-55°C, Package Quantity=1, Supplier Part Number 1=96M1132, Temperature Coefficient=30ppm/°C, Tolerance=5%, Voltage=50V
C14: library part C1005X5R1A225K050BC, "TDK - C1005X5R1A225K050BC - COND, CERÁ MULT, X5R, 2.2UF, 10V, 0402", Manufacturer=TDK, Supplier Part Number 1=2346879
D1: "Blue 0402 1X.5X4MM", Case Code (Imperial)=0402, Case Code (Metric)=1005, Color=Blue, Forward Voltage=2.8V, Lens Color=Colorless, Manufacturer="American Bright", Test Current=20mA
D2: "Red 0402 1X.5X4MM", Case Code (Imperial)=0402, Case Code (Metric)=1005, Color=Red, Forward Voltage=2V, Lens Color=Colorless, Manufacturer="American Bright", Test Current=20mA
J4: library part PICO-DEVELOP-PORT, "DSpico Development port", Current Rating=?, Manufacturer=LNH, Max Operating Temperature=85°C, Min Operating Temperature=-25°C, Voltage Rating=3.3V
Q1 Q2: "P-Channel 30 V 3.5A (Tc) 1.1W (Ta), 1.8W (Tc) Surface Mount SOT-23-3 (TO-236)", Case/Package=SOT23-3, Drain Current-Max (Abs) (ID)=3.5A, Drain-source On Resistance-Max=88mR, DS Breakdown Voltage-Min=30V, Max Operating Temperature=150°C, Operating Mode="ENHANCEMENT MODE", Package Body Material=Plastic, Package Shape=Rectangular, Package Style="SMALL OUTLINEMeter", Peak Reflow Temperature (Cel)=260°C, Power Dissipation-Max (Abs)=1.8W, Time @ Peak Reflow Temperature-Max (s)=30s
Q3: "MOSFETs SOT-23", Case/Package=SOT-23, Continuous Drain Current (ID)=380mA, Gate to Source Voltage (Vgs)=20V, Manufacturer="Diodes Zetex", Max Operating Temperature=150°C, Min Operating Temperature=-55°C, Power Dissipation=540mW
R1 R2: library part CRCW0402100KFKED, "RES SMD 100K OHM 1% 1/16W 0402", Case Code (Imperial)=0402, Case Code (Metric)=1005, Manufacturer=Vishay, Max Operating Temperature=155°C, Max Power Dissipation=63mW, Min Operating Temperature=-55°C, Package Quantity=10000, Resistance=100kR, Supplier Part Number 1=1469671, Temperature Coefficient=100ppm/°C, Tolerance=1%, Voltage Rating=50V
R3 R4 R5 R6 R7 R8 R9: library part CRCW040210K0FKED, "VISHAY DRALORIC - CRCW040210K0FKED - RESISTENCIA, 10K, 0.063W, 1%, 0402, SMD", Case Code (Imperial)=0402, Case Code (Metric)=1005, Manufacturer=Vishay, Max Operating Temperature=155°C, Max Power Dissipation=63mW, Min Operating Temperature=-55°C, Package Quantity=10, Resistance=10kR, Supplier Part Number 1=1469669, Temperature Coefficient=100ppm/°C, Tolerance=1%, Voltage Rating=50V
R10 R11: "RES 27 OHM 1% 1/16W 0402", Case/Package=0402, Max Operating Temperature=155°C, Min Operating Temperature=-55°C, Package Height=0.35mm, Package Length=1mm, Package Shape=Rectangular, Package Style=SMTMeter, Package Width=0.5mm, Rated Power Dissipation (P)=62.5mW, Rated Temperature=70°C, Resistance=27R, Resistor Type="FIXED RESISTOR", Temperature Coefficient=100ppm/°C, Tolerance=1%, Working Voltage=50V
R12: library part RC0402FR-07120RL, "Res General Purpose Thick Film 0402 120 Ohm 1% 1/16W ±100ppm/°C Molded Paper T/R", Case Code (Imperial)=0402, Case Code (Metric)=1005, Manufacturer=Yageo, Max Operating Temperature=155°C, Max Power Dissipation=63mW, Min Operating Temperature=-55°C, Package Quantity=1, Power Rating=62.5mW, Resistance Tolerance=1%, Resistor Type="Thick Film", Supplier Part Number 1=9239120, Temperature Coefficient=100ppm/°C, Voltage Rating=50V
R13: library part RC0402FR-07220RL, "SMD Chip Resistor, 220 Ohm, ± 1%, 62.5 mW, 0402 [1005 Metric], Thick Film, General Purpose", Case Code (Imperial)=0402, Case Code (Metric)=1005, Manufacturer=Yageo, Max Operating Temperature=155°C, Max Power Dissipation=63mW, Min Operating Temperature=-55°C, Package Quantity=1, Power Rating=62.5mW, Resistance Tolerance=1%, Resistor Type="Thick Film", Supplier Part Number 1=9239154, Temperature Coefficient=100ppm/°C, Voltage Rating=50V
R14 R15: library part CRCW04021K00FKEDC, "VISHAY - CRCW04021K00FKED - RES, PELÍC GRUESA, 1K, 1%, 0.063W, 0402", Coeficiente de Temperatura="± 100", Manufacturer=VISHAY, Manufacturer Part Number=CRCW04021K00FKED, Rango de Temperatura de Funcionamiento="-55°C a +155", Resistencia=1, Resistencia, Montaje="Dispositivo de Montaje Superficial (SMD)", Supplier Part Number 1=1469662, Temperatura de Trabajo Máx.=155, Temperatura de Trabajo Mín.="-55°C<!--FANDB--><div class{}\"features-and-benefits-container\"><div class{}\"features-and-benefits-description\"><span class{}\"features-benefits-value\">The Vishay D/CRCW e3 series are standard thick film chip resistors. The resistance range includes E96 and E24 decade values from 1ohm to 10Mohm. CRCW e3 series resistors have a pure tin solder contacts on the Ni barrier layer that provides compatibility with reflow soldering process.</span></div><div class{}\"features-and-benefits-list\"><ul class{}\"features-and-benefits-list-list\"><li class{}\"features-and-benefits-list-item\">Automotive grade AEC-Q200 qualified</li><li class{}\"features-and-benefits-list-item\">EIA 0402, 0603, 0805, 1206, 1210, 1218, 2010, 2512 standard case sizes available</li><li class{}\"features-and-benefits-list-item\">Stability &Delta", Tipo de Elemento Resistivo="Película Gruesa", Tipo de Resistencia="0402 [Métrica 1005]", Tolerancia de Resistencia="± 1%"
S1: "Switch Tactile N.O. SPST Rectangular Button Gull Wing 0.05A 12VDC 1.6N SMD T/R", Manufacturer="Alps Electric"
U1: "IC REG LDO 3.3V 0.6A SOT25", Case/Package=SOT-23-5, Dropout Voltage=250mV, Manufacturer=Diodes, Max Input Voltage=6V, Max Operating Temperature=85°C, Max Output Current=600mA, Min Input Voltage=2.5V, Min Operating Temperature=-40°C, Output Voltage=3.3V, Package Quantity=1, Quiescent Current=55uA, Supplier Part Number 1=8043011
U2: "RP2040 chip for Raspberry Pi Pico - ARM Cortex-M0+ MCU 32-Bit", Package=None
U3: "NOR Flash Serial (SPI, Dual SPI, Quad SPI) 3V/3.3V 16M-bit 2M x 8 6ns 8-Pin USON EP T/R", Package="UFDFN-8 Winbond"

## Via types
v1: diameter 0.46, hole 0.2, L1 to L4, tented both sides, 68 vias
v2: diameter 0.65, hole 0.25, L1 to L4, tented both sides, 59 vias

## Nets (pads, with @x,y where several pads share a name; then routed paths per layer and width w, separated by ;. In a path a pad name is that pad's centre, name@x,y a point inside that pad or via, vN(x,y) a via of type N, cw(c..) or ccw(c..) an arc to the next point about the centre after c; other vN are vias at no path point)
+1V1: C9.2 C10.2 C11.2 U2.23 U2.45 U2.50 | length 7.6
  L1 w0.2: C11.2@19.85,22.01 20.1,21.76 U2.50 20.1,20.26 20.026,20.186 19.94,20.1 v1(19.9,20.1) ; v1(20.6,14.86) 20.9,14.56 20.9,13.56 21.3,13.16 C10.2@21.3,12.76 ; v1(21.8,20.1) 22.1,20.4 22.1,21.319 22.466,21.685 23.025,21.685 C9.2
+3V3: C3.2 C4.2 C5.2 C6.2 C7.2 C8.2 C14.2 C15.2 J1.4 J4.3 Q1.2 Q2.2 R2.2 R3.2 R4.2 R5.2 R6.2 R7.2 R8.2 R9.2 U2.1 U2.10 U2.22 U2.33 U2.42 U2.43 U2.44 U2.48 U2.49 U3.8 | length 28.4
  L1 w0.2: R6.2@1.155,13.655 R6.2 R5.2 2.4,13.7 2.466,13.634 v1(3.133,13.634) ; R4.2 v1(3.8,15.2) ; J1.4@7.5,28.496 J1.4@7.52,28.476 ; v1(14.1,14.06) R7.2 ; v2(15.186,18.446) 15.186,18.474 15.1,18.56 C3.2 ; C5.2 U2.10 ; C4.2 15.404,20.064 16.861,20.064 U2.1 ; v2(17.898,25.935) 17.898,25.303 17.878,25.282 C14.2 C15.2 U3.8 ; C6.2@20.1,12.76 20.433,13.093 20.433,13.493 20.5,13.56 U2.22 ; C6.2 v2(20.6,12.76) ; U2.49 20.5,20.282 20.7,20.082 20.9,20.282 U2.48 U2.48@20.9,21.215 ; U2.44 22.5,20.282 22.7,20.082 22.9,20.282 U2.43 ; v2(22.55,11.26) 22.55,11.71 R3.2 ; U2.33 25.05,16.46 25.1,16.51 C7.2@25.1,16.57 ; U2.42 C8.2 25.05,19.91 25.23,19.91 25.28,19.86 v1(25.35,19.86) ; C7.2 25.23,16.49 25.67,16.49 v1(25.674,16.494)
  L1 w0.3: R9.2 v1(6.016,15.195) ; Q2.2 9.5,14.3 9.7,14.1 v2(9.7,13.9) ; v2(10.595,13.5) R2.2 ; v1(11.9,14.1) R8.2 ; C5.2 15.317,16.543 15.317,16.911 15.367,16.96 v2(15.441,16.96)
  L1 w0.4: v2(7.5,27.7) J1.4@7.5,28.496 ; Q1.2 10.95,11.152 11.15,11.352 11.552,11.352 v2(11.6,11.4) ; C3.2 C4.2
  L4 w0.7: v2(7.5,27.7) 8.24,28.44 J4.3@8.24,30.5
  other v2: 20.7,19.96 22.7,19.96
+3V3_BUS: C2.2 Q1.1 Q2.3 Q3.1 R1.1 R15.1 U1.5 | length 18.4
  L1 w0.2: R1.1 12.4,13.5 12.4,12.967 v2(12.417,12.95) ; R15.1 v1(26.1,14.1)
  L1 w0.6: v2@12.8,11.95 v2(12.81,11.95) 12.81,11.19 Q1.1
  L3-PW w0.2: v2(12.81,11.95) 14.45,11.95 16,10.4 23.1,10.4 24.2,11.5 24.2,13.1 25.2,14.1 v1(26.1,14.1)
  other v2: 5.2,11.2 7.3,12.3 5.7,13.4
+3V3_DS: J3.8 Q1.3 | length 6
  L1 w0.4: v2@11.4,8.2 11.4,8.35 Q1.3
  L1 w0.6: J3.8 11.163,3.163 11.163,5.802 v2(11.167,5.806)
  L3-PW w0.8: v2@11.205,5.794 11.205,8.08 v2(11.325,8.2)
+VBUS: C1.2 J2.1 U1.1 U1.3 | length 3.4
  L1 w0.3: v2(2,10.1) 2.025,10.125 2.79,10.125 U1.3 ; v2(2,12.1) 2.025,12.075 2.79,12.075 U1.1 ; v2(3.5,8.4) C1.2 ; J2.1 21.9,26.024 v2(21.9,24.86)
CLK_DS: J3.2 U2.14 | length 22.7
  L1 w0.2: J3.2 2.159,5.802 3.457,7.1 12.04,7.1 14.7,9.76 14.7,12.86 16.545,14.705 16.545,14.86 U2.14
CLK_SD: J1.5 R9.1 U2.5 | length 26.1
  L1 w0.2: v1(15.9,18.26) 15.97,18.26 16.17,18.46 U2.5
  L1 w0.3: R9.1 7.112,14.791 7.427,14.791 7.45,14.813 v1@7.45,14.821 ; R9.1@7.016,14.745 7.116,14.845 7.145,14.845 8.62,16.32 J1.5
  L4 w0.2: v1(7.501,14.821) 10.54,17.86 15.5,17.86 v1(15.9,18.26)
CMD: J1.3 R4.1 U2.6 | length 30.4
  L1 w0.2: U2.6 17.76,18.06 v1(17.9,18.2)
  L1 w0.3: v1(5.2,14.6) 5.169,14.631 4.869,14.631 R4.1 4.8,15.49 6.42,17.11 J1.3@6.42,28.476
  L4 w0.2: v1(5.2,14.6) 5.239,14.6 5.473,14.366 8.966,14.366 10.4,15.8 12.427,15.8 14.137,17.51 15.864,17.51 16.554,18.2 v1(17.9,18.2)
D0: J3.9 U2.15 | length 13.6
  L1 w0.2: v1(17.349,14.309) 17.385,14.345 17.7,14.345 U2.15
  L1 w0.3: J3.9@12.632,3.459 12.8,3.627 12.667,3.76 12.667,5.806 12.706,5.806 v2@12.8,5.9
  L4 w0.2: v2@12.8,5.9 12.8,9.76 v1(17.349,14.309)
  other v2: 12.663,5.806
D1: J3.10 U2.16 | length 14.2
  L1 w0.2: v1(17.732,14.876) 17.732,14.817 18.1,14.449 U2.16
  L1 w0.3: J3.10@14.154,3.459 14.3,3.605 14.205,3.7 14.205,5.8 14.205,5.805 v2@14.3,5.9
  L4 w0.2: v2@14.205,5.8 14.205,10.165 17.804,13.764 17.804,14.803 v1(17.732,14.876)
  other v2: 14.159,5.806
D2: J3.11 U2.17 | length 14.1
  L1 w0.2: v1(18.37,14.822) 18.5,14.692 U2.17
  L1 w0.3: J3.11@15.808,3.459 15.8,3.467 15.818,3.485 15.696,3.607 15.696,5.783 15.786,5.783 v2@15.818,5.815
  L4 w0.2: v2@15.696,5.783 19.1,9.187 19.1,14.092 v1(18.37,14.822)
  other v2: 15.656,5.806
D3: J3.12 U2.18 | length 13.7
  L1 w0.2: U2.18 18.9,14.694 18.985,14.78 v1(18.985,14.85)
  L1 w0.3: v2@17.152,5.783 17.152,3.86 17.3,3.712 17.123,3.534 J3.12@17.198,3.459
  L4 w0.2: v2@17.152,5.783 19.6,8.231 19.6,14.16 18.985,14.774 v1(18.985,14.85)
  other v2: 17.152,5.806
D4: J3.13 U2.27 | length 13
  L1 w0.2: J3.13 18.659,5.819 23.2,10.36 23.2,13.06 23.025,13.235 22.617,13.235 22.5,13.352 U2.27
D5: J3.14 U2.28 | length 12.6
  L1 w0.2: J3.14 20.159,6.073 23.744,9.657 23.744,13.473 23.191,14.025 U2.28
D6: J3.15 U2.29 | length 12.9
  L1 w0.2: J3.15 21.659,6.228 24.3,8.869 24.3,14.66 24.1,14.86 U2.29
D7: J3.16 U2.30 | length 13.4
  L1 w0.2: J3.16 23.159,6.359 24.825,8.025 24.825,14.935 24.5,15.26 U2.30
D_N: J2.2 R10.1 | length 3.4
  L1 w0.26: J2.2@21.215,26.004 21.215,24.64 21.894,23.961 21.894,23.432 22.046,23.28 22.18,23.28 R10.1
D_P: J2.3 R11.1 | length 3.4
  L1 w0.26: J2.3@20.5,25.923 20.624,25.799 20.624,25.136 20.8,24.96 20.8,24.507 21.506,23.801 21.506,23.432 21.354,23.28 21.22,23.28 R11.1
DAT0: J1.7 R8.1 U2.7 | length 23.5
  L1 w0.2: U2.7 17.77,17.66 17.852,17.577 v1@17.922,17.577
  L1 w0.3: J1.7@10.8,28.476 10.8,14.8 R8.1
  L4 w0.2: v1(10.804,15.192) 11.35,14.645 14.945,14.645 v1(17.9,17.6)
DAT1: J1.8 R7.1 U2.8 | length 19.3
  L1 w0.2: v1(16.258,17.26) U2.8
  L1 w0.3: 11.9,15.95 13.1,14.75 R7.1 ; 11.9,16.05 11.9,28.456 J1.8@11.92,28.476
  L4 w0.2: v1(12.8,15.1) 14,16.3 15.64,16.3 16.254,16.914 16.254,17.256 v1(16.258,17.26)
DAT2: J1.1 R6.1 U2.9 | length 37.5
  L1 w0.2: U2.9 17.836,16.86 v1(17.901,16.795)
  L1 w0.3: v1(1.48,14.622) 1.48,14.659 1.469,14.669 1.169,14.669 R6.1 1.1,14.7 1.1,14.95 1.1,15 1.1,16.4 4.22,19.52 J1.1@4.22,28.476
  L4 w0.2: v1(1.48,14.622) 1.53,14.672 1.53,14.83 5.696,18.996 15.414,18.996 15.664,18.745 17.998,18.745 18.355,18.388 18.355,17.249 v1(17.901,16.795)
DAT3: J1.2 R5.1 U2.11 | length 33.2
  L1 w0.2: U2.11 v1(17.6,16.06)
  L1 w0.3: R5.1@2.25,14.6 R5.1@2.412,14.763 ; v1(3,14.6) 2.575,14.6 R5.1@2.412,14.763 ; J1.2@5.32,28.476 5.3,28.456 5.3,17.65 2.575,14.925 R5.1@2.412,14.763
  L4 w0.2: v1(3,14.6) 4.75,12.85 11.539,12.85 12.189,13.5 13.645,13.5 14.64,13.5 17.2,16.06 v1(17.6,16.06)
GND: C1.1 C2.1 C3.1 C4.1 C5.1 C6.1 C7.1 C8.1 C9.1 C10.1 C11.1 C12.1 C13.1 C14.1 C15.1 D1.1 D2.1 J1.6 J1.11 J1.12 J1.13 J1.14 J2.5 J2.6 J2.7 J2.8 J2.9 J3.1 J3.17 J4.6 Q3.2 R1.2 S1.1 S1.3 S1.4 U1.2 U2.19 U2.57 U3.4 U3.9 X1.2 X1.4 | length 31.7
  L1 w0.2: v2(3.8,12.7) C2.1 ; v2(4.5,8.4) C1.1 ; v2(7.3,8.7) 7.3,9.2 Q3.2 ; R1.2@13.381,13.625 13.331,13.575 13.331,13.036 v2(13.417,12.95) ; v2(13.8,20.06) C4.1 C4.1@14.3,19.96 ; v1@14.3,21.36 14.342,21.36 14.642,21.66 15.05,21.66 U3.4 ; C5.1 v2(14.4,16.9) ; v2(14.4,18.41) C3.1 ; U3.9 16.519,22.441 16.519,21.518 v2(16.539,21.499) ; C15.1 17,24.06 v2(17,23.56) ; C14.1 v2(16.9,25.96) ; J2.5@19.141,26.573 19.254,26.46 J2.5 ; U2.19 19.3,14.449 19.664,14.813 v2@19.664,14.879 ; v1@19.331,23.201 19.355,23.177 19.883,23.177 C11.1 ; v2@19.585,14.8 v2@19.664,14.879 ; v2(19.664,14.895) v2@19.664,14.879 ; v2(20.2,11.26) C6.1 ; v2(21.4,11.26) C10.1 ; C9.1 23.51,23.17 v1(23.51,23.595) ; v2(24.1,21.26) 24.794,21.26 S1.1 ; S1.3 25.878,22.66 v2(25.928,22.61) ; C8.1 25.413,19.06 v1(25.477,18.996) ; C7.1 25.455,17.46 25.413,17.502 25.682,17.502 v1(25.722,17.462)
  L1 w0.25: C12.1 15.464,10.796 15.464,10.394 v2(16.226,9.631) ; v2@16.255,9.805 16.436,9.985 16.475,9.985 16.9,10.41 X1.2 17.325,10.885 17.325,11.085 17.975,11.735 17.975,11.935 X1.4 ; v2@16.287,9.692 16.895,9.085 16.975,9.085 C13.1
  L1 w0.4: v2(2,11.1) U1.2 ; v1(9.7,27.7) J1.6@9.7,28.476 ; 13.548,30.56 13.579,30.529 14.069,30.529 D1.1 14.1,30.474 14.17,30.404 15.335,30.404 J2.9 ; v2(14,27.3) 14.048,27.252 14.048,26.79 D2.1 D2.1@14.1,26.621 ; v2(18.7,26.586) 18.713,26.573 J2.5@19.141,26.573
  L1 w0.6: J3.1@0.8,3.303 v2(0.8,5.8) ; v2(24.8,5.8) 24.8,2.967 J3.17@24.808,2.959
  L4 w0.2: v2@19.582,14.977 v2(19.664,14.895)
  L4 w0.7: J4.6@0.62,30.5 0.688,30.432 v2(1.519,30.432)
  other v1: 4.1,6.2 24.1,6.2 0.6,7.2 1.6,7.2 2.6,7.2 13.6,7.2 15.6,7.2 25.6,7.2 15.1,8.2 16.1,8.2 17.1,8.2 5.6,9.2 15.6,9.2 20.6,9.2 25.6,9.2 0,13.4 14.323,21.47 13.4,21.9 19.416,23.193 0.6,27.2 2.1,28.2 9.5,31.1
  other v2: 19.3,16.46 21.3,16.46 19.3,18.46 21.3,18.46
IRQ: J3.7 U2.31 | length 25.6
  L1 w0.2: v1(22.9,15.6) 22.96,15.66 U2.31
  L1 w0.3: J3.7@9.588,3.459 9.564,3.483 9.8,3.718 9.685,3.833 v2@9.685,5.794
  L4 w0.2: v2@9.685,5.794 9.806,5.794 10.4,5.2 19.84,5.2 23.1,8.46 23.1,15.4 v1(22.9,15.6)
  other v2: 9.67,5.806
LED_B: R12.2 U2.40 | length 24.6
  L1 w0.2: R12.2@15.044,28.154 15.156,28.154 15.1,28.21 R12.2 ; U2.40 24.263,19.26 24.38,19.143 24.38,18.762 24.611,18.53 24.649,18.53 24.672,18.507 24.7,18.48 v1(24.7,18.4)
  L1 w0.4: R12.2 15.139,28.299 v2(15.675,28.299)
  L4 w0.2: v2(15.675,28.299) 15.467,28.299 14.55,27.383 14.55,25.836 14.992,25.394 15.051,25.335 15.22,25.335 ccw(c15.429,26.159) 15.638,25.335 18.275,25.335 19.763,26.823 23.437,26.823 25.3,24.96 25.3,20.9 24.7,20.3 v1(24.7,18.4)
LED_R: R13.2 U2.39 | length 16.5
  L1 w0.2: v1(22.854,18.951) 22.944,18.86 U2.39
  L1 w0.35: R13.2@15.175,24.585 15.175,24.425 v2(15.97,23.63)
  L4 w0.2: v2(15.97,23.63) 16.45,24.11 21.928,24.11 22.233,24.415 22.764,24.415 23.03,24.149 23.03,22.33 21.345,20.645 21.345,19.911 22.306,18.951 v1(22.854,18.951)
NetC12_2: C12.2 U2.20 X1.1 | length 5.5
  L1 w0.2: X1.1 16.9,12.41 17.683,13.193 19.292,13.193 19.7,13.601 U2.20
  L1 w0.25: C12.2 15.471,11.931 16.475,11.931 16.9,12.356 X1.1
NetC13_2: C13.2 U2.21 X1.3 | length 5.9
  L1 w0.2: X1.3 18.4,10.51 19.175,11.285 19.175,12.617 20.1,13.542 U2.21
  L1 w0.25: C13.2 18.1,10.16 X1.3
NetD1_2: D1.2 R12.1 | length 1.4
  L1 w0.2: D1.2@13.938,29.26 D1.2
  L1 w0.4: R12.1 D1.2
NetD2_2: D2.2 R13.1 | length 1.1
  L1 w0.4: R13.1@14.1,24.66 D2.2@14.1,25.722
NetQ2_1: Q2.1 Q3.3 R2.1 | length 3.9
  L1 w0.5: Q2.1@9.7,12.5 R2.1
  L1 w0.6: Q3.3 Q2.1 Q2.1@9.7,12.5
NetR3_1: R3.1 U2.26 | length 1.4
  L1 w0.2: U2.26 22.1,13.21 22.5,12.81 R3.1@22.5,12.76
NetR14_1: R14.1 S1.2 | length 1.4
  L1 w0.2: R14.1 23.6,24.41 23.75,24.26 23.8,24.26 24.012,24.048 S1.2
NetR15_2: R15.2 U2.36 | length 5.8
  L1 w0.2: U2.36 24.389,17.66 24.674,17.945 24.888,17.945 25.882,17.945 26.177,17.65 26.177,15.31 25.983,15.116 25.516,15.116 R15.2
QSPI_SCLK: U2.52 U3.6 | length 2.5
  L1 w0.2: U3.6@17.6,22.21 18.468,22.21 19.3,21.378 U2.52
QSPI_SD0: U2.53 U3.5 | length 1.6
  L1 w0.2: U3.5 17.948,21.71 17.951,21.713 18.506,21.713 18.9,21.319 U2.53
QSPI_SD1: U2.55 U3.2 | length 6.8
  L1 w0.2: v1(14.3,22.66) 14.362,22.722 14.375,22.735 15.075,22.735 U3.2 U3.2@15.125,22.685 ; v1(18.1,20.16) U2.55
  L4 w0.2: v1(14.3,22.66) 14.37,22.66 14.485,22.545 14.535,22.545 14.88,22.2 16.616,22.2 18.1,20.716 v1(18.1,20.16)
QSPI_SD2: U2.54 U3.3 | length 7.7
  L1 w0.2: v1@14.2,22.06 14.2,22.003 14.287,22.003 14.493,22.21 U3.3 ; U2.54 18.5,20.457 18.776,20.181 v1(18.776,20.104)
  L4 w0.2: v1@14.2,22.06 14.37,22.06 14.475,21.955 14.545,21.955 16.795,19.705 17.301,19.705 17.311,19.715 17.688,19.715 17.698,19.705 18.378,19.705 v1(18.776,20.104)
  other v1: 14.3,22.06
QSPI_SD3: U2.51 U3.7 | length 2.9
  L1 w0.2: U3.7 18.445,22.71 19.7,21.455 U2.51
QSPI_SS: R14.2 U2.56 U3.1 | length 15
  L1 w0.2: v1@14.2,23.26 15.05,23.26 U3.1 ; U3.1@15.128,23.16 15.568,23.16 15.92,22.808 15.92,21.262 16.422,20.76 17.7,20.76 U2.56 ; v1(22.575,23.96) 22.588,23.973 22.588,24.448 R14.2
  L4 w0.2: v1(14.34,23.245) 14.39,23.195 14.605,23.195 15.1,22.7 21.315,22.7 v1(22.575,23.96)
ROM_CS: J3.4 U2.13 | length 20.3
  L1 w0.2: U2.13 17.43,15.26 17.63,15.46 v1(17.7,15.46)
  L1 w0.3: J3.4@4.987,3.494 5.3,3.808 5.182,3.926 v2@5.182,5.707
  L4 w0.2: v2@5.182,5.707 5.393,5.707 5.885,5.215 6.769,5.215 8.112,6.558 8.558,6.558 17.41,15.41 17.65,15.41 v1(17.7,15.46)
  other v2: 5.182,5.806
RST_DS: J3.5 U2.12 | length 20.4
  L1 w0.2: v2(6.509,8.1) 9.1,8.1 10.9,9.9 13.458,9.9 14,10.442 14,13.2 14.6,13.8 14.6,14.06 16.2,15.66 U2.12
  L1 w0.3: v2(6.533,5.806) 6.533,3.585 J3.5@6.6,3.518 ; J3.5 6.659,3.92 J3.5@6.662,3.923
  L4 w0.2: v2(6.509,8.1) 6.589,8.02 6.589,6.016 6.662,5.943 v2@6.662,5.765
SPI_CS: J3.6 U2.32 | length 28.7
  L1 w0.2: U2.32 24.23,16.06 24.43,15.86 v1(24.5,15.86)
  L1 w0.3: J3.6@8.1,3.493 8.174,3.567 v2(8.174,5.806)
  L4 w0.2: v2@8.3,5.9 9.6,4.6 20.3,4.6 24.3,8.6 24.3,15.613 24.5,15.813 v1(24.5,15.86)
SWCLK: J4.2 U2.24 | length 30.8
  L1 w0.2: U2.24 v1(21.3,14.86) v1@21.3,14.96
  L4 w0.2: J4.2@10.78,30.5 10.8,30.48 10.8,25.957 12.212,24.545 19.845,24.545 20.71,25.41 22.95,25.41 24.1,24.26 24.1,22.16 23.3,21.36 23.3,19.148 23.309,19.139 23.309,18.762 23.3,18.753 23.3,17.6 21.3,15.6 v1(21.3,14.86)
SWD: J4.1 U2.25 | length 29.4
  L1 w0.2: U2.25 21.7,14.59 21.9,14.79 v1(21.9,14.86)
  L4 w0.2: J4.1@13.32,30.5 13.3,30.48 13.3,25.9 14.24,24.96 19.06,24.96 20.2,26.1 23.3,26.1 24.7,24.7 24.7,21.06 24,20.36 24,17.6 21.95,15.55 21.95,14.91 v1(21.9,14.86)
UART_RX: J4.5 U2.3 | length 21.6
  L1 w0.2: U2.3 17.67,19.26 17.73,19.2 v1@17.8,19.2
  L4 w0.2: J4.5@3.16,30.5 3.16,28.34 10.89,20.61 14.35,20.61 15.806,19.154 17.754,19.154 v1@17.8,19.2
  other v1: 17.9,19.2
UART_TX: J4.4 U2.2 | length 17.2
  L1 w0.2: v1@15.999,19.559 16.069,19.559 v1(16.12,19.609) 16.17,19.66 U2.2
  L4 w0.2: J4.4@5.7,30.5 5.7,28.1 12.785,21.015 14.61,21.015 15.893,19.732 15.927,19.732 16.049,19.609 v1(16.12,19.609)
USB_D_N: R10.2 U2.46 | length 1.6
  L1 w0.26: U2.46 21.694,20.901 21.694,21.688 22.046,22.04 22.18,22.04 R10.2
USB_D_P: R11.2 U2.47 | length 1.4
  L1 w0.26: R11.2 21.15,22.16 21.27,22.04 21.27,21.924 21.306,21.888 21.306,20.901 U2.47
pads on no net: J1.9 J1.10 J2.4 J3.3 U1.4 U2.4 U2.34 U2.35 U2.37 U2.38 U2.41

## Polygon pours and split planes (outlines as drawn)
GND on L3-PW "NONET_L-01_P-001" (solid, remove dead copper, pour order 14): -2.8,37 29.9,37 29.9,-3.5 -2.8,-3.5
+VBUS on L3-PW "NONET_L-01_P-001" (solid, pour order 8): 22.6,22.76 10.64,22.76 8.8,24.6 8.8,27.8 8.2,28.4 7.166,28.4 6.592,27.826 6.592,24.192 2.606,20.206 2.606,12.994 3.9,11.7 3.9,8.2 3.46,7.76 2,7.76 -0.181,9.941 -0.181,24.319 6.066,30.566 11.334,30.566 13.354,28.546 13.354,26.853 15.008,25.2 22.6,25.2
+3V3 on L3-PW "NONET_L-01_P-001" (solid, remove dead copper, pour order 9): 8.3,28 8.3,24.56 10.36,22.5 22.14,22.5 23,23.36 23,25.2 17.4,25.2 17.4,26.16 24.267,26.167 25.234,25.2 25.234,23.034 23.226,21.011 21.11,20.979 21.105,20.622 25.949,20.622 26.014,15.714 23.226,12.743 23.226,10.8 22.3,10.8 21.196,11.904 16.172,11.904 14.399,13.7 11.9,13.7 11.9,11.06 9.7,11.06 6.5,14.26 4.6,14.26 3.562,13.222 2.6,13.222 2.601,19.801 6.896,24.096 6.896,28
+1V1 on L3-PW "NONET_L-01_P-001" (solid, pour order 3): 19.465,20.53 20.282,20.53 20.282,19.881 21.272,19.666 21.279,20.622 22.3,20.622 22.3,15.9 21,14.6 20.4,14.6 19.9,15.1 19.866,19.169 19.465,19.571
+3V3_BUS on L3-PW "NONET_L-01_P-001" (solid, pour order 10): 5.416,13.86 6.4,13.86 9.4,10.86 12.1,10.86 12.1,13.265 13.5,13.265 13.5,10.26 12.631,9.391 6.37,9.39 4.7,11.06 4.699,13.143
GND on L1 "NONET_L-01_P-001" (solid, remove dead copper, pour order 12): -2.8,37 29.9,37 29.9,-3.5 -2.8,-3.5
+3V3_BUS on L1 "NONET_L-01_P-001" (solid, pour order 5): 4.1,13.8 4.1,11.4 4.9,10.6 8.2,10.6 8.2,13.8
no net on L1 "NONET_L-01_P-001" (solid, pour order 1): 0,0
GND on L4 "NONET_L-01_P-001" (solid, remove dead copper, pour order 13): -2.8,37 29.9,37 29.9,-3.5 -2.8,-3.5
GND on L2-GND (split plane): 189 vertices, not listed, extent 0.009,0.009 26.204,30.99

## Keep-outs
L1:
  region: 8.08,15.083

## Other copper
L1:
  pour cut-out: 15.71,24.509 16.524,24.509 16.6,24.433 16.6,23.9 15.946,23.9 15.7,24.146
  pour cut-out: 17.104,24.613 17.104,25 17.5,25 17.511,24.989 17.511,24.624
  pour cut-out: 14.736,14.606 14.736,18.26 15.9,18.26 15.9,14.596
  pour cut-out: 13.636,17.446 13.636,15.236 11.6,15.236 11.6,17.446
  pour cut-out: 12.7,17.4
  pour cut-out: 8.2,13.8 9.2,13.8 9.2,10.4 8.2,10.4
  pour cut-out: 8.2,10.294
  pour cut-out: 17.6,19.9 22.64,19.9 22.693,19.953 22.693,15.101 17.701,15.101 17.7,15.1
  pour cut-out: 1.468,29.422 12,29.422 12,15.1 1.468,15.1
L4:
  pour cut-out: 24.408,17.817 24.408,9.208 23.3,8.1 22.9,8.5 22.9,16.2
  pour cut-out: 13.777,22.177 13.777,24.3 15.6,24.3 15.6,22.149
  pour cut-out: -0.038,30.618 -0.296,30.618 -0.355,30.677 -0.355,31.123 -0.03,31.123 -0.028,31.125
  pour cut-out: 15.3,21.9 18.4,21.9 18.4,19.6 18.3,19.5 16.9,19.5 16.9,19.565 14.51,21.955

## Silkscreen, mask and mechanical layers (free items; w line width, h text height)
Top Overlay:
  text "p" at 9.388,5.947 h0.95
  text "L" at 0.388,5.89 h0.95
  text "N" at 1.842,5.89 h0.95
  text "H" at 3.342,5.89 h0.95
  text "D" at 6.342,5.89 h0.95
  text "S" at 7.842,5.89 h0.95
  text "i" at 11.023,5.89 h0.95
  text "c" at 12.388,5.89 h0.95
  text "o" at 13.865,5.89 h0.95
  text "V" at 16.797,5.89 h0.95
  text "1" at 18.546,5.89 h0.95
  text "." at 20.114,5.89 h0.95
  text "3" at 21.342,5.89 h0.95
  text "-" at 4.752,5.483 h0.95
  text "-" at 15.252,5.483 h0.95
Bottom Overlay:
  drawing of 4 lines, arcs and shapes, not listed
  text "LNH team" at 23.5,3.1 h1.5
  text "PCB BY '.Company'  '.Year'" at 23,1.4 h1.55
  text "'.Project' '.VersionRevision'" at 17.9,0.6 h2
Bottom Solder:
  region: 1401 vertices and 10 holes, not listed, extent 0.399,0.909 4.922,5.562
Board:
  lines w0.013: -0.502,-0.101 -0.502,-0.002 -0.502,10.444 -0.502,10.507 -0.452,10.621 -0.361,10.706 -0.243,10.748 -0.181,10.743 -0.032,10.743 0.26,10.803 0.525,10.94 0.743,11.143 0.898,11.398 0.978,11.684 0.978,11.982 0.898,12.269 0.743,12.523 0.525,12.727 0.26,12.863 -0.032,12.923 -0.181,12.923 -0.243,12.919 -0.361,12.96 -0.452,13.045 -0.502,13.16 -0.502,13.222 -0.502,31 -0.502,31.099 -0.426,31.283 -0.285,31.424 -0.101,31.5 16.554,31.5 16.554,27.224 24.511,27.224 24.511,31.5 26.314,31.5 26.498,31.424 26.638,31.283 26.715,31.099 26.715,31 26.715,13.222 26.715,13.16 26.665,13.045 26.573,12.96 26.456,12.919 26.393,12.923 26.244,12.923 25.952,12.863 25.688,12.727 25.47,12.523 25.315,12.269 25.234,11.982 25.234,11.684 25.315,11.398 25.47,11.143 25.688,10.94 25.952,10.803 26.244,10.743 26.393,10.743 26.456,10.748 26.573,10.706 26.665,10.621 26.715,10.507 26.715,10.444 26.715,0.728 26.715,0.678 26.695,0.582 26.658,0.491 26.603,0.409 26.568,0.374 25.839,-0.355 25.804,-0.39 25.722,-0.445 25.631,-0.483 25.534,-0.502 25.485,-0.502 -0.002,-0.502 -0.101,-0.502 -0.285,-0.426 -0.426,-0.285 -0.502,-0.101
Top 3D Body:
  circle w0.013: c21.099,26.488 r1.3
  circle w0.013: c5.113,26.491 r1.3
  lines w0.013: 0.259,0.828 0.259,8.715 ; 1.485,0.747 1.485,8.466 ; 21.012,1.812 22.22,1.812 ; 23.924,0.756 23.924,6.996 ; 25.195,0.678 25.195,7.231
Mechanical 4:
  circle w0.01: c21.216,25.998 r1.2
  circle w0.01: c5.15,25.998 r1.2
Mechanical 7:
  lines w0.2: -4.3,9.2 31.1,9.2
